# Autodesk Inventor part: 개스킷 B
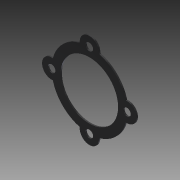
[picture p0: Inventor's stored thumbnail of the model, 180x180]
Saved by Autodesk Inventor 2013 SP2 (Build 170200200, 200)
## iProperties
Created: 2020-03
Part Number: 개스킷 B
Material: 고무
Document SubType Name: Modeling
Designer: mduedu
Density: 0.93 g/cm^3
Mass: 1.13966 g
Surface Area: 28.6179 cm^2
Volume: 1.22544 cm^3
Author: mduedu
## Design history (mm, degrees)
sketch "스케치1" dims "d1" = 55
  geometry: C1 r 21 at (0, 0); C2 r 7 at (0, 27.5); C3 r 7 at (-23.816, -13.75); C4 r 7 at (23.816, -13.75); 2 further points
  constraints: 4 centre point, 2 coincident, 2 vertical alignment, 9 other
  dimensions: "d0" = 42 diameter of C1; "d2" = 14 diameter of C2; "d5" = 360 deg dimension on point (0, 0) C2.centre (derived)
extrude "돌출1" new body sketch "스케치1" distance "d7" = 1; taper "d8" = 0 deg
extrude "돌출3" join sketch "스케치1" stored distance "d19" = 10; taper "d20" = 0 deg
fillet "모깎기1" dims "d11" = 1
extrude "돌출2" cut sketch "스케치1" stored distance "d9" = 1; taper "d10" = 0 deg
sketch "스케치2"
  geometry: C1 r 21 at (0, 0) reference; A1 r 7 centre (0, 27.5) between (6.999, 27.373) and (-6.999, 27.373) reference; A2 r 27.5 centre (0, 0) between (26.609, 6.943) and (7.718, 26.395) reference; A3 r 1 centre (7.999, 27.355) between (6.999, 27.373) and (7.718, 26.395) reference; A4 r 7 centre (0, 27.5) between (6.999, 27.373) and (-6.999, 27.373) reference; A5 r 1 centre (-7.999, 27.355) between (-7.718, 26.395) and (-6.999, 27.373) reference; A6 r 7 centre (0, -27.5) between (-6.943, -26.609) and (6.943, -26.609) reference; A7 r 7 centre (-27.5, 0) between (-26.609, 6.943) and (-26.609, -6.943) reference; A8 r 7 centre (27.5, 0) between (26.609, -6.943) and (26.609, 6.943) reference; A9 r 27.5 centre (0, 0) between (-26.609, -6.943) and (-6.943, -26.609) reference; A10 r 27.5 centre (0, 0) between (6.943, -26.609) and (26.609, -6.943) reference; A11 r 27.5 centre (0, 0) between (-7.718, 26.395) and (-26.609, 6.943) reference; 4 further points
hole "구멍1" sketch "스케치2" diameter "d12" = 5.5; stored, may be unused: countersink angle "d16" = 90 deg, drill point angle "d18" = 118 deg; dims "d13" = 6, "d14" = 4, "d15" = 2, "d17" = 8
node "솔리드1"
pattern_circular "원형 패턴1" dims angle "d22" = 360 deg
node "투영된 루프1"
